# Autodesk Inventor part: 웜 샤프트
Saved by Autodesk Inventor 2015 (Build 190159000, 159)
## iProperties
Created: 2025-06
Part Number: 웜 샤프트
Material: 일반
Document SubType Name: Modeling
Designer: 104
Density: 1 g/cm^3
Appearance: 기본값
Author: 104
Author: jhkim
Creation Date: 2025-05-23
Sending System: Autodesk Inventor 2026
Preprocessor: ST-DEVELOPER v20.1
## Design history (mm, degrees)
node "웜 샤프트1"
body "Solid1"
node "기준1"
